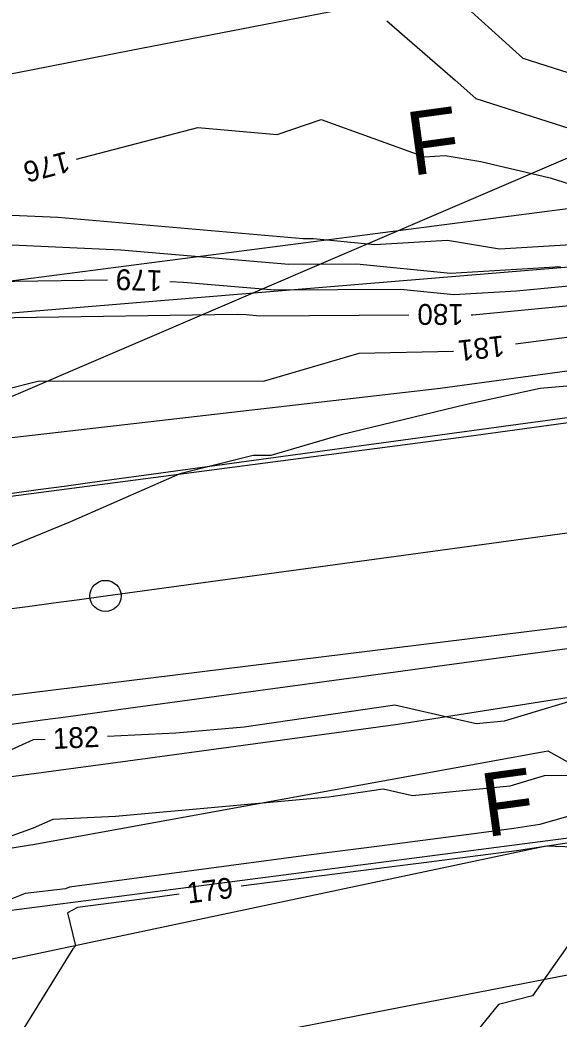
# Model space of a CAD drawing. Extents: x 2086416 to 2115205, y 575507 to 632762.
# Drawn here: x 2111423.3 to 2111475.2, y 581597.8 to 581693.8 of the extents above; entities that cross this region are included whole.
import ezdxf

# ---------------------------------------------------------------- set-up
doc = ezdxf.new("R2010")
doc.units = 0
for name, color, linetype in [('DTM Contours Major', 7, 'Continuous'), ('DTM Contours Major Text', 7, 'Continuous'), ('DTM Contours Minor', 7, 'Continuous'), ('DTM Contours Minor Text', 7, 'Continuous'), ('Exist Hydrographic FEMA Cross Section', 7, 'Continuous'), ('Exist Right of Way Line', 7, 'Continuous'), ('Exist Roads EOP', 7, 'Continuous'), ('Exist Vegetation Woods Line', 7, 'Continuous'), ('Prop EOT', 7, 'Continuous'), ('Prop Horizontal Alignment', 7, 'Continuous'), ('Prop Horizontal Alignment Station Label', 7, 'Continuous'), ('Prop Paved Shoulder', 7, 'Continuous'), ('Prop SS Fill Line', 7, 'Continuous'), ('Prop SS Fill Text', 7, 'Continuous')]:
    doc.layers.add(name, color=color, linetype=linetype)

msp = doc.modelspace()

# ---------------------------------------------------------------- linework, layer by layer
at = {"layer": 'DTM Contours Major'}
for points in [[(2111458.614, 581693.725), (2111465.19, 581688.009), (2111467.154, 581686.234), (2111480.824, 581681.896)], [(2111466.726, 581665.442), (2111466.87, 581665.45), (2111492.781, 581667.943)], [(2111362.56, 581651.297), (2111363.859, 581651.417), (2111367.3, 581652.098), (2111378.59, 581655.678), (2111384.736, 581656.959), (2111410.782, 581663.456), (2111412.038, 581663.856), (2111412.764, 581664.298), (2111416.283, 581665.011), (2111422.788, 581665.196), (2111444.213, 581665.517), (2111445.076, 581665.479), (2111446.412, 581665.364), (2111460.735, 581665.466)], [(2111501.468, 581623.557), (2111493.699, 581622.176), (2111485.498, 581619.952), (2111473.32, 581616.448), (2111470.815, 581616.065), (2111467.705, 581615.666), (2111457.917, 581614.372), (2111451.074, 581613.494), (2111428.1, 581610.449), (2111427.715, 581610.257), (2111423.838, 581609.834), (2111421.598, 581608.92), (2111416.907, 581607.541), (2111403.297, 581606.115)]]:
    msp.add_lwpolyline(points, dxfattribs=at)
at = {"layer": 'DTM Contours Minor'}
for points in [[(2111463.727, 581697.326), (2111471.697, 581690.122), (2111480.45, 581687.344)], [(2111368.765, 581694.561), (2111373.18, 581690.967), (2111376.213, 581688.421), (2111374.988, 581684.477), (2111374.345, 581683.964), (2111375.283, 581682.859), (2111378.114, 581684.026), (2111383.988, 581686.435), (2111393.453, 581684.581), (2111404.868, 581681.588), (2111405.004, 581681.538), (2111416.402, 581676.167), (2111417.82, 581675.764), (2111421.041, 581675.098), (2111426.984, 581674.836), (2111450.574, 581672.799), (2111451.554, 581672.806), (2111457.455, 581672.204), (2111464.428, 581672.63), (2111469.437, 581671.797), (2111479.516, 581672.403), (2111482.882, 581672.727), (2111491.534, 581672.68)], [(2111428.771, 581680.412), (2111440.431, 581683.453), (2111448.076, 581682.788), (2111452.292, 581684.247), (2111462.234, 581680.656), (2111464.205, 581680.777), (2111467.66, 581680.202), (2111474.313, 581678.633), (2111481.198, 581676.448)], [(2111422.551, 581672.178), (2111433.015, 581671.717), (2111449.186, 581670.321), (2111455.738, 581670.367), (2111464.732, 581669.45), (2111475.3, 581670.085)], [(2111437.733, 581668.656), (2111439.046, 581668.598), (2111447.799, 581667.842), (2111459.922, 581667.929), (2111465.054, 581667.406), (2111471.085, 581667.768), (2111489.481, 581669.538)], [(2111317.904, 581663.351), (2111356.866, 581661.826), (2111360.408, 581661.794), (2111360.456, 581661.012), (2111366.133, 581663.304), (2111375.003, 581662.984), (2111382.899, 581662.078), (2111397.839, 581664.459), (2111412.985, 581667.48), (2111414.577, 581667.747), (2111414.665, 581667.763), (2111418.312, 581668.622), (2111431.738, 581668.823)], [(2111514.426, 581665.768), (2111514.076, 581666.505), (2111514.07, 581666.377), (2111513.681, 581666.938), (2111513.593, 581666.892), (2111513.813, 581666.05), (2111514.217, 581665.091), (2111513.834, 581664.627), (2111513.623, 581664.386), (2111501.864, 581662.752), (2111499.925, 581662.768), (2111499.461, 581662.71), (2111495.816, 581660.338), (2111473.348, 581658.369), (2111466.15, 581656.804), (2111454.207, 581653.913), (2111447.466, 581651.924), (2111445.759, 581651.927), (2111438.707, 581650.157), (2111428.197, 581645.562), (2111418.247, 581641.471)], [(2111470.971, 581662.653), (2111489.767, 581665.106)], [(2111269.918, 581624.058), (2111270.71, 581624.172), (2111275.888, 581625.032), (2111295.143, 581628.295), (2111310.242, 581631.559), (2111319.393, 581633.414), (2111333.072, 581637.242), (2111339.352, 581639.052), (2111342.163, 581639.082), (2111342.18, 581639.377), (2111344.603, 581639.49), (2111345.711, 581639.592), (2111368.058, 581644.016), (2111371.035, 581644.959), (2111390.012, 581648.914), (2111399.542, 581651.291), (2111412.87, 581655.543), (2111414.88, 581656.764), (2111417.768, 581657.244), (2111425.188, 581659.107), (2111446.75, 581659.064), (2111455.965, 581661.783), (2111465.015, 581661.958)], [(2111431.761, 581624.957), (2111438.318, 581625.266), (2111444.88, 581625.862), (2111459.383, 581627.95), (2111467.209, 581626.166), (2111469.917, 581626.437), (2111480.37, 581629.578)], [(2111420.357, 581622.71), (2111424.643, 581624.622), (2111425.768, 581624.675)], [(2111481.177, 581621.169), (2111473.746, 581621.131), (2111470.433, 581620.135), (2111461.073, 581619.199), (2111458.251, 581619.843), (2111453.021, 581619.09), (2111432.526, 581617.227), (2111426.482, 581616.943), (2111424.588, 581616.098), (2111421.118, 581614.849)], [(2111512.897, 581612.943), (2111502.542, 581616.244), (2111495.925, 581612.318), (2111495.047, 581609.681), (2111493.145, 581612.369), (2111486.486, 581613.505), (2111483.671, 581613.737), (2111483.198, 581613.6), (2111482.119, 581613.436), (2111472.626, 581599.987), (2111469.34, 581599.165), (2111466.838, 581596.068), (2111463.884, 581593.537), (2111423.2, 581580.097), (2111421.166, 581578.021), (2111413.921, 581573.833), (2111415.71, 581582.768), (2111413.83, 581586.352), (2111407.094, 581599.119), (2111404.077, 581600.927), (2111385.483, 581590.707), (2111395.032, 581602.545), (2111389.517, 581602.876), (2111380.322, 581601.494)], [(2111478.259, 581615.024), (2111471.081, 581613.927), (2111462.169, 581612.782), (2111458.615, 581612.313), (2111444.604, 581610.516)], [(2111438.653, 581609.752), (2111436.08, 581609.422), (2111428.873, 581608.467), (2111427.89, 581607.976), (2111428.685, 581604.782), (2111428.43, 581604.516), (2111422.37, 581594.713), (2111411.165, 581598.812), (2111409.519, 581598.944), (2111408.822, 581600.274), (2111408.399, 581601.076), (2111407.646, 581601.527), (2111399.001, 581606.017), (2111389.746, 581605.283), (2111373.81, 581602.888), (2111368.567, 581602.556), (2111362.088, 581601.979), (2111346.112, 581598.33)]]:
    msp.add_lwpolyline(points, dxfattribs=at)
at = {"layer": 'Exist Hydrographic FEMA Cross Section'}
for points in [[(2111558.917, 581715.133), (2111549.307, 581713.264), (2111539.703, 581711.399), (2111530.094, 581709.529), (2111520.484, 581707.66), (2111510.88, 581705.795), (2111501.271, 581703.925), (2111491.662, 581702.061), (2111482.057, 581700.191), (2111472.448, 581698.321), (2111462.838, 581696.457), (2111453.235, 581694.587), (2111443.625, 581692.717), (2111434.016, 581690.852), (2111424.411, 581688.983), (2111414.802, 581687.113), (2111405.193, 581685.248), (2111395.589, 581683.378), (2111385.979, 581681.508), (2111376.37, 581679.644), (2111366.766, 581677.774), (2111357.156, 581675.91), (2111347.547, 581674.04)], [(2111658.777, 581615.589), (2111477.281, 581602.232), (2111476.99, 581602.175), (2111467.38, 581600.311), (2111457.771, 581598.441), (2111448.167, 581596.571), (2111438.557, 581594.706), (2111428.948, 581592.837), (2111419.344, 581590.967), (2111409.734, 581589.102), (2111400.125, 581587.233), (2111390.521, 581585.363), (2111380.911, 581583.498), (2111371.307, 581581.628), (2111361.698, 581579.759), (2111352.088, 581577.894)]]:
    msp.add_lwpolyline(points, dxfattribs=at)
at = {"layer": 'Exist Right of Way Line'}
for points in [[(2111371.804, 581662.16), (2111512.522, 581680.421)], [(2111379.525, 581602.659), (2111520.243, 581620.919)]]:
    msp.add_lwpolyline(points, dxfattribs=at)
at = {"layer": 'Exist Roads EOP'}
for points in [[(2111417.782, 581647.422), (2111417.782, 581647.422), (2111466.254, 581653.757), (2111515.092, 581660.442), (2111516.542, 581650.631)], [(2111419.52, 581628.553), (2111419.52, 581628.553), (2111468.663, 581634.583), (2111518.005, 581640.729), (2111516.542, 581650.631)]]:
    msp.add_lwpolyline(points, dxfattribs=at)
at = {"layer": 'Exist Vegetation Woods Line'}
for points in [[(2111452.102, 581736.219), (2111479.268, 581697.501), (2111499.678, 581677.784), (2111492.037, 581671.336), (2111416.636, 581665.128), (2111367.277, 581660.929), (2111318.174, 581654.198), (2111268.317, 581650.615), (2111220.664, 581649.448), (2111173.288, 581649.119), (2111125.979, 581651.571), (2111078.275, 581655.724), (2111059.793, 581657.645)], [(2111257.868, 581581.404), (2111333.104, 581590.969), (2111406.178, 581600.069), (2111473.936, 581614.42), (2111501.631, 581613.416), (2111525.035, 581604.65), (2111555.787, 581590.729), (2111597.414, 581531.022), (2111635.4, 581485.12), (2111692.38, 581438.808), (2111736.925, 581397.696), (2111757.961, 581379.063)]]:
    msp.add_lwpolyline(points, dxfattribs=at)
at = {"layer": 'Prop EOT'}
for p, q in [((2111430.061, 581649.328), (2112312.029, 581769.688)), ((2111433.036, 581627.53), (2112315.004, 581747.89))]:
    msp.add_line(p, q, dxfattribs=at)
for radius in [2331.03, 2353.03]:
    msp.add_arc((2111114.873, 583958.951), radius, 273.818067, 277.771006, dxfattribs=at)
at = {"layer": 'Prop Horizontal Alignment'}
msp.add_line((2111431.548, 581638.429), (2112404.465, 581771.2), dxfattribs=at)
msp.add_arc((2111114.873, 583958.951), 2342.03, 273.818067, 277.771006, dxfattribs=at)
at = {"layer": 'Prop Horizontal Alignment Station Label'}
msp.add_circle((2111431.548, 581638.429), 1.5, dxfattribs=at)
at = {"layer": 'Prop Paved Shoulder'}
for p, q in [((2111498.903, 581663.18), (2111463.748, 581658.382)), ((2111463.748, 581658.382), (2111414.175, 581652.664)), ((2111459.664, 581626.117), (2111488.488, 581630.64)), ((2111433.712, 581622.576), (2111459.664, 581626.117))]:
    msp.add_line(p, q, dxfattribs=at)
msp.add_arc((2111114.873, 583958.951), 2358.03, 275.149984, 277.771006, dxfattribs=at)
at = {"layer": 'Prop SS Fill Line'}
for p, q in [((2111419.256, 581656.202), (2111481.214, 581682.795)), ((2111424.759, 581614.575), (2111474.094, 581623.547)), ((2111374.858, 581606.533), (2111424.759, 581614.575))]:
    msp.add_line(p, q, dxfattribs=at)
msp.add_lwpolyline([(2111474.094, 581623.547), (2111485.015, 581617.465)], dxfattribs=at)

# ---------------------------------------------------------------- texts
at = {"layer": 'DTM Contours Major Text'}
msp.add_text('180', height=2, rotation=179.76623, dxfattribs=at).set_placement((2111466.014, 581666.478))
at = {"layer": 'DTM Contours Minor Text'}
for s, rotation, p in [('176', 194.6174, (2111427.818, 581681.197)), ('179', 178.4055, (2111437.039, 581669.724)), ('181', 186.65941, (2111469.804, 581663.483)), ('182', 2.69592, (2111426.539, 581623.71)), ('179', 7.30975, (2111439.499, 581608.852))]:
    msp.add_text(s, height=2, rotation=rotation, dxfattribs=at).set_placement(p)
at = {"layer": 'Prop SS Fill Text'}
for p in [(2111461.013, 581678.814), (2111468.165, 581615.239)]:
    msp.add_text('F', height=6.104, rotation=7.77101, dxfattribs=at).set_placement(p)

doc.saveas('drawing.dxf')
